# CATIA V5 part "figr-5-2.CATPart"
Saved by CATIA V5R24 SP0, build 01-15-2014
Part number: Part1
Bounding box of the stored display mesh (mm): x -23 to 23, y -104 to 104, z 0 to 68
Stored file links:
  D:\KAVITA\CATIA V5-6R2014 Project_ Kavita\CATIA V5-6R2014_partfiles\Partfiles\c05_catia_v5-6r2014_prt\figr-5-2.CATPart
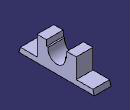
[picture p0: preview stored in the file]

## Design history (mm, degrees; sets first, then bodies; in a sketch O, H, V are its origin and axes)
Sketch1 on yz-plane, origin (0, 0, 0), H (0, 1, 0), V (0, 0, 1)
  line L1 (0, 0) -> (104, 0)
  point P1 (104, 0)
  line L2 (104, 0) -> (100, 14)
  point P2 (100, 14)
  line L3 (100, 14) -> (54, 14)
  point P3 (54, 14)
  line L4 (54, 14) -> (54, 68)
  point P4 (54, 68)
  line L5 (54, 68) -> (28, 68)
  point P5 (28, 68)
  line L6 (28, 68) -> (28, 52)
  point P6 (28, 52)
  line L7 (28, 52) -> (23.6643, 52)
  axis line L8 (0, 0) -> (0, 150)
  point P8 (0, 0)
  construction line L9 through (0, 0) direction (-1, 0)
  construction line L10 through (0, 0) direction (0, 1)
  point P13 (-104, 0)
  point P14 (-100, 14)
  point P15 (-54, 14)
  point P16 (-54, 68)
  point P17 (-28, 68)
  point P18 (-28, 52)
  line L11 (0, 0) -> (-104, 0)
  line L12 (-104, 0) -> (-100, 14)
  line L13 (-100, 14) -> (-54, 14)
  line L14 (-54, 14) -> (-54, 68)
  line L15 (-54, 68) -> (-28, 68)
  line L16 (-28, 68) -> (-28, 52)
  line L17 (-28, 52) -> (-23.6643, 52)
  arc A1 centre (0, 48) radius 24 from (-23.6643, 52) to (23.6643, 52) ccw
  point P19 (0, 48)
  point P20 (13.2665, 68)
  distance P1 P13 = 208
  length L2 V = 14
  length L2 H = 4
  distance L4 L14 = 108
  distance L16 L6 = 56
  distance L1 L5 = 68
  length L6 = 16
  distance P19 L7 = 4
  radius A1 = 24
  horizontal: L1 H, L3 H, L5 H, L7 H
  vertical: L4 V, L6 V, L8 V
  symmetry: O P8 L8, H L9 L8, V L10 L8, P1 P13 L8, P2 P14 L8, P3 P15 L8, P4 P16 L8, P5 P17 L8, P6 P18 L8, L1 L11 L8, L2 L12 L8, L3 L13 L8, L4 L14 L8, L5 L15 L8, L6 L16 L8, L7 L17 L8
  coincidence: P19 L8, A1 P20, P20 L5, O P8
Pad1: profile Sketch1, direction (1, 0, 0), length 23, mirrored extent
Body1 (main body)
